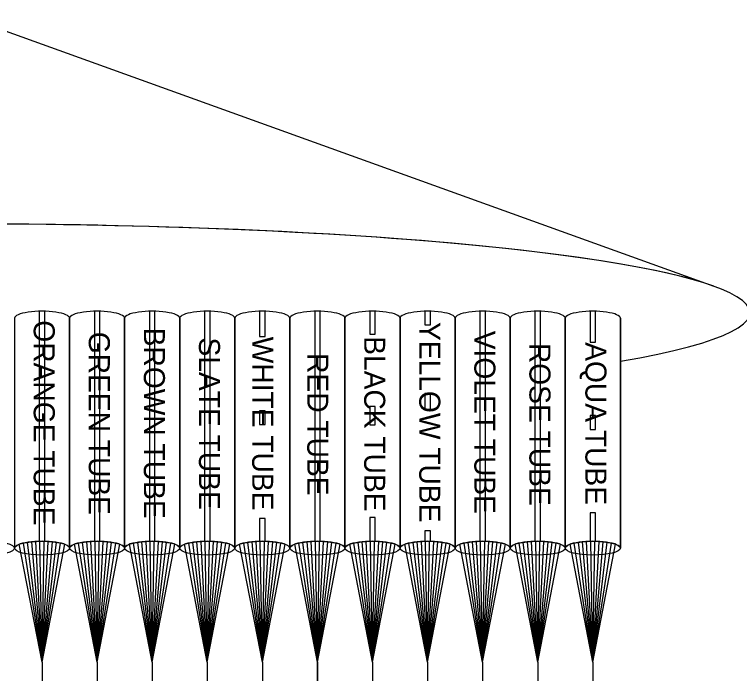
# Model space of a CAD drawing. Extents: x 1805893 to 1833564, y 708898 to 716199.
# Drawn here: x 1831827.8 to 1831906.8, y 715537.7 to 715609.5 of the extents above; entities that cross this region are included whole.
import ezdxf

# ---------------------------------------------------------------- set-up
doc = ezdxf.new("R2010")
doc.units = 0
doc.layers.add('SH_Data', color=7, linetype='Continuous')

msp = doc.modelspace()

# ---------------------------------------------------------------- linework, layer by layer
at = {"layer": 'SH_Data'}
for p, q in [((1831827.844, 715576.44), (1831827.844, 715551.39)), ((1831833.844, 715576.44), (1831833.844, 715551.39)), ((1831833.844, 715551.39), (1831833.844, 715576.44)), ((1831839.844, 715551.39), (1831839.844, 715576.44)), ((1831839.844, 715576.44), (1831839.844, 715551.39)), ((1831845.844, 715551.39), (1831845.844, 715576.44)), ((1831845.844, 715576.44), (1831845.844, 715551.39)), ((1831851.844, 715551.39), (1831851.844, 715576.44)), ((1831851.844, 715576.44), (1831851.844, 715551.39)), ((1831857.844, 715551.39), (1831857.844, 715576.44)), ((1831857.844, 715576.44), (1831857.844, 715551.39)), ((1831863.844, 715551.39), (1831863.844, 715576.44)), ((1831863.844, 715576.44), (1831863.844, 715551.39)), ((1831869.844, 715576.44), (1831869.844, 715551.39)), ((1831869.844, 715551.39), (1831869.844, 715576.44)), ((1831875.844, 715551.39), (1831875.844, 715576.44)), ((1831875.844, 715576.44), (1831875.844, 715551.39)), ((1831881.844, 715551.39), (1831881.844, 715576.44)), ((1831881.844, 715576.44), (1831881.844, 715551.39)), ((1831887.844, 715551.39), (1831887.844, 715576.44)), ((1831887.844, 715576.44), (1831887.844, 715551.39)), ((1831893.844, 715551.39), (1831893.844, 715576.44)), ((1831893.844, 715576.44), (1831893.844, 715551.39)), ((1831893.844, 715551.39), (1831893.844, 715571.748)), ((1831830.844, 715538.969), (1831828.369, 715551.813)), ((1831830.844, 715538.969), (1831828.819, 715551.943)), ((1831830.844, 715538.969), (1831829.269, 715552.028)), ((1831830.844, 715538.969), (1831829.719, 715552.085)), ((1831830.844, 715538.969), (1831830.169, 715552.12)), ((1831830.844, 715538.969), (1831830.619, 715552.137)), ((1831830.844, 715538.969), (1831831.069, 715552.137)), ((1831830.844, 715538.969), (1831831.519, 715552.12)), ((1831830.844, 715538.969), (1831831.969, 715552.085)), ((1831830.844, 715538.969), (1831832.419, 715552.028)), ((1831830.844, 715538.969), (1831832.869, 715551.943)), ((1831830.844, 715538.969), (1831833.319, 715551.813)), ((1831836.844, 715538.969), (1831834.369, 715551.813)), ((1831836.844, 715538.969), (1831834.819, 715551.943)), ((1831836.844, 715538.969), (1831835.269, 715552.028)), ((1831836.844, 715538.969), (1831835.719, 715552.085)), ((1831836.844, 715538.969), (1831836.169, 715552.12)), ((1831836.844, 715538.969), (1831836.619, 715552.137)), ((1831836.844, 715538.969), (1831837.069, 715552.137)), ((1831836.844, 715538.969), (1831837.519, 715552.12)), ((1831836.844, 715538.969), (1831837.969, 715552.085)), ((1831836.844, 715538.969), (1831838.419, 715552.028)), ((1831836.844, 715538.969), (1831838.869, 715551.943)), ((1831836.844, 715538.969), (1831839.319, 715551.813)), ((1831842.844, 715538.969), (1831840.369, 715551.813)), ((1831842.844, 715538.969), (1831840.819, 715551.943)), ((1831842.844, 715538.969), (1831841.269, 715552.028)), ((1831842.844, 715538.969), (1831841.719, 715552.085)), ((1831842.844, 715538.969), (1831842.169, 715552.12)), ((1831842.844, 715538.969), (1831842.619, 715552.137)), ((1831842.844, 715538.969), (1831843.069, 715552.137)), ((1831842.844, 715538.969), (1831843.519, 715552.12)), ((1831842.844, 715538.969), (1831843.969, 715552.085)), ((1831842.844, 715538.969), (1831844.419, 715552.028)), ((1831842.844, 715538.969), (1831844.869, 715551.943)), ((1831842.844, 715538.969), (1831845.319, 715551.813)), ((1831848.844, 715538.969), (1831846.369, 715551.813)), ((1831848.844, 715538.969), (1831846.819, 715551.943)), ((1831848.844, 715538.969), (1831847.269, 715552.028)), ((1831848.844, 715538.969), (1831847.719, 715552.085)), ((1831848.844, 715538.969), (1831848.169, 715552.12)), ((1831848.844, 715538.969), (1831848.619, 715552.137)), ((1831848.844, 715538.969), (1831849.069, 715552.137)), ((1831848.844, 715538.969), (1831849.519, 715552.12)), ((1831848.844, 715538.969), (1831849.969, 715552.085)), ((1831848.844, 715538.969), (1831850.419, 715552.028)), ((1831848.844, 715538.969), (1831850.869, 715551.943)), ((1831848.844, 715538.969), (1831851.319, 715551.813)), ((1831854.844, 715538.969), (1831852.369, 715551.813)), ((1831854.844, 715538.969), (1831852.819, 715551.943)), ((1831854.844, 715538.969), (1831853.269, 715552.028)), ((1831854.844, 715538.969), (1831853.719, 715552.085)), ((1831854.844, 715538.969), (1831854.169, 715552.12)), ((1831854.844, 715538.969), (1831854.619, 715552.137)), ((1831854.844, 715538.969), (1831855.069, 715552.137)), ((1831854.844, 715538.969), (1831855.519, 715552.12)), ((1831854.844, 715538.969), (1831855.969, 715552.085)), ((1831854.844, 715538.969), (1831856.419, 715552.028)), ((1831854.844, 715538.969), (1831856.869, 715551.943)), ((1831854.844, 715538.969), (1831857.319, 715551.813)), ((1831860.844, 715538.969), (1831858.369, 715551.813)), ((1831860.844, 715538.969), (1831858.819, 715551.943)), ((1831860.844, 715538.969), (1831859.269, 715552.028)), ((1831860.844, 715538.969), (1831859.719, 715552.085)), ((1831860.844, 715538.969), (1831860.169, 715552.12)), ((1831860.844, 715538.969), (1831860.619, 715552.137)), ((1831860.844, 715538.969), (1831861.069, 715552.137)), ((1831860.844, 715538.969), (1831861.519, 715552.12)), ((1831860.844, 715538.969), (1831861.969, 715552.085)), ((1831860.844, 715538.969), (1831862.419, 715552.028)), ((1831860.844, 715538.969), (1831862.869, 715551.943)), ((1831860.844, 715538.969), (1831863.319, 715551.813)), ((1831866.844, 715538.969), (1831864.369, 715551.813)), ((1831866.844, 715538.969), (1831864.819, 715551.943)), ((1831866.844, 715538.969), (1831865.269, 715552.028)), ((1831866.844, 715538.969), (1831865.719, 715552.085)), ((1831866.844, 715538.969), (1831866.169, 715552.12)), ((1831866.844, 715538.969), (1831866.619, 715552.137)), ((1831866.844, 715538.969), (1831867.069, 715552.137)), ((1831866.844, 715538.969), (1831867.519, 715552.12)), ((1831866.844, 715538.969), (1831867.969, 715552.085)), ((1831866.844, 715538.969), (1831868.419, 715552.028)), ((1831866.844, 715538.969), (1831868.869, 715551.943)), ((1831866.844, 715538.969), (1831869.319, 715551.813)), ((1831872.844, 715538.969), (1831870.369, 715551.813)), ((1831872.844, 715538.969), (1831870.819, 715551.943)), ((1831872.844, 715538.969), (1831871.269, 715552.028)), ((1831872.844, 715538.969), (1831871.719, 715552.085)), ((1831872.844, 715538.969), (1831872.169, 715552.12)), ((1831872.844, 715538.969), (1831872.619, 715552.137)), ((1831872.844, 715538.969), (1831873.069, 715552.137)), ((1831872.844, 715538.969), (1831873.519, 715552.12)), ((1831872.844, 715538.969), (1831873.969, 715552.085)), ((1831872.844, 715538.969), (1831874.419, 715552.028)), ((1831872.844, 715538.969), (1831874.869, 715551.943)), ((1831872.844, 715538.969), (1831875.319, 715551.813)), ((1831878.844, 715538.969), (1831876.369, 715551.813)), ((1831878.844, 715538.969), (1831876.819, 715551.943)), ((1831878.844, 715538.969), (1831877.269, 715552.028)), ((1831878.844, 715538.969), (1831877.719, 715552.085)), ((1831878.844, 715538.969), (1831878.169, 715552.12)), ((1831878.844, 715538.969), (1831878.619, 715552.137)), ((1831878.844, 715538.969), (1831879.069, 715552.137)), ((1831878.844, 715538.969), (1831879.519, 715552.12)), ((1831878.844, 715538.969), (1831879.969, 715552.085)), ((1831878.844, 715538.969), (1831880.419, 715552.028)), ((1831878.844, 715538.969), (1831880.869, 715551.943)), ((1831878.844, 715538.969), (1831881.319, 715551.813)), ((1831884.844, 715538.969), (1831882.369, 715551.813)), ((1831884.844, 715538.969), (1831882.819, 715551.943)), ((1831884.844, 715538.969), (1831883.269, 715552.028)), ((1831884.844, 715538.969), (1831883.719, 715552.085)), ((1831884.844, 715538.969), (1831884.169, 715552.12)), ((1831884.844, 715538.969), (1831884.619, 715552.137)), ((1831884.844, 715538.969), (1831885.069, 715552.137)), ((1831884.844, 715538.969), (1831885.519, 715552.12)), ((1831884.844, 715538.969), (1831885.969, 715552.085)), ((1831884.844, 715538.969), (1831886.419, 715552.028)), ((1831884.844, 715538.969), (1831886.869, 715551.943)), ((1831884.844, 715538.969), (1831887.319, 715551.813)), ((1831890.844, 715538.969), (1831888.369, 715551.813)), ((1831890.844, 715538.969), (1831888.819, 715551.943)), ((1831890.844, 715538.969), (1831889.269, 715552.028)), ((1831890.844, 715538.969), (1831889.719, 715552.085)), ((1831890.844, 715538.969), (1831890.169, 715552.12)), ((1831890.844, 715538.969), (1831890.619, 715552.137)), ((1831890.844, 715538.969), (1831891.069, 715552.137)), ((1831890.844, 715538.969), (1831891.519, 715552.12)), ((1831890.844, 715538.969), (1831891.969, 715552.085)), ((1831890.844, 715538.969), (1831892.419, 715552.028)), ((1831890.844, 715538.969), (1831892.869, 715551.943)), ((1831890.844, 715538.969), (1831893.319, 715551.813)), ((1831830.844, 715538.969), (1831830.844, 715504.211)), ((1831830.844, 715538.969), (1831830.844, 715504.211)), ((1831836.844, 715538.969), (1831836.844, 715504.211)), ((1831836.844, 715538.969), (1831836.844, 715504.211)), ((1831842.844, 715538.969), (1831842.844, 715504.211)), ((1831842.844, 715538.969), (1831842.844, 715504.211)), ((1831848.844, 715538.969), (1831848.844, 715504.211)), ((1831848.844, 715538.969), (1831848.844, 715504.211)), ((1831854.844, 715538.969), (1831854.844, 715504.211)), ((1831854.846, 715538.969), (1831854.86, 715504.211)), ((1831860.844, 715504.211), (1831860.844, 715538.969)), ((1831860.844, 715538.969), (1831860.844, 715504.211)), ((1831866.844, 715538.969), (1831866.844, 715504.211)), ((1831866.844, 715538.969), (1831866.844, 715504.211)), ((1831872.844, 715538.969), (1831872.844, 715504.211)), ((1831872.844, 715538.969), (1831872.844, 715504.211)), ((1831878.844, 715538.969), (1831878.844, 715504.211)), ((1831878.844, 715538.969), (1831878.844, 715504.211)), ((1831884.844, 715538.969), (1831884.844, 715504.211)), ((1831884.844, 715538.969), (1831884.844, 715504.211)), ((1831890.844, 715538.969), (1831890.844, 715504.211)), ((1831890.846, 715538.969), (1831890.86, 715504.211))]:
    msp.add_line(p, q, dxfattribs=at)
msp.add_lwpolyline([(1831739.647, 715579.916), (1831821.844, 715609.509), (1831904.04, 715579.916)], dxfattribs=at)
msp.add_lwpolyline([(1831739.647, 715579.916), (1831821.844, 715609.509), (1831904.04, 715579.916)], dxfattribs=at)
for points in [[(1831830.544, 715577.186), (1831830.544, 715552.138), (1831831.144, 715552.138), (1831831.144, 715577.186)], [(1831836.544, 715577.186), (1831836.544, 715552.138), (1831837.144, 715552.138), (1831837.144, 715577.186)], [(1831842.544, 715577.186), (1831842.544, 715552.138), (1831843.144, 715552.138), (1831843.144, 715577.186)], [(1831848.544, 715577.186), (1831848.544, 715552.138), (1831849.144, 715552.138), (1831849.144, 715577.186)], [(1831854.544, 715577.186), (1831854.544, 715574.46), (1831855.144, 715574.46), (1831855.144, 715577.186)], [(1831860.544, 715577.186), (1831860.544, 715552.138), (1831861.144, 715552.138), (1831861.144, 715577.186)], [(1831866.544, 715577.186), (1831866.544, 715574.709), (1831867.144, 715574.709), (1831867.144, 715577.186)], [(1831872.544, 715577.186), (1831872.544, 715575.722), (1831873.144, 715575.722), (1831873.144, 715577.186)], [(1831878.544, 715577.186), (1831878.544, 715552.138), (1831879.144, 715552.138), (1831879.144, 715577.186)], [(1831884.544, 715577.186), (1831884.544, 715552.138), (1831885.144, 715552.138), (1831885.144, 715577.186)], [(1831890.544, 715577.186), (1831890.544, 715573.818), (1831891.144, 715573.818), (1831891.144, 715577.186)], [(1831872.544, 715568.222), (1831872.544, 715566.502), (1831873.144, 715566.502), (1831873.144, 715568.222)], [(1831866.544, 715566.809), (1831866.544, 715564.837), (1831867.144, 715564.837), (1831867.144, 715566.809)], [(1831854.544, 715566.354), (1831854.544, 715564.87), (1831855.144, 715564.87), (1831855.144, 715566.354)], [(1831890.544, 715565.823), (1831890.544, 715564.305), (1831891.144, 715564.305), (1831891.144, 715565.823)], [(1831854.544, 715554.623), (1831854.544, 715552.136), (1831855.144, 715552.136), (1831855.144, 715554.623)], [(1831866.544, 715554.744), (1831866.544, 715552.136), (1831867.144, 715552.136), (1831867.144, 715554.744)], [(1831890.544, 715555.239), (1831890.544, 715552.136), (1831891.144, 715552.136), (1831891.144, 715555.239)], [(1831872.544, 715553.264), (1831872.544, 715552.136), (1831873.144, 715552.136), (1831873.144, 715553.264)]]:
    msp.add_lwpolyline(points, close=True, dxfattribs=at)
for centre, major_axis, ratio, start_param, end_param in [((1831821.844, 715577.043), (86.094, 0), 0.112175, 5.702888, 10.005075), ((1831821.844, 715577.043), (86.094, 0), 0.112175, 5.702888, 10.005075), ((1831821.844, 715577.043), (86.094, 0), 0.112175, 0.302036, 2.839557), ((1831830.844, 715576.44), (3, 0), 0.25, 0, 3.141593), ((1831830.844, 715576.44), (3, 0), 0.25, 0, 3.141593), ((1831836.844, 715576.44), (3, 0), 0.25, 0, 3.141593), ((1831836.844, 715576.44), (3, 0), 0.25, 0, 3.141593), ((1831842.844, 715576.44), (3, 0), 0.25, 0, 3.141593), ((1831842.844, 715576.44), (3, 0), 0.25, 0, 3.141593), ((1831848.844, 715576.44), (3, 0), 0.25, 0, 3.141593), ((1831848.844, 715576.44), (3, 0), 0.25, 0, 3.141593), ((1831854.844, 715576.44), (3, 0), 0.25, 0, 3.141593), ((1831854.844, 715576.44), (3, 0), 0.25, 0, 3.141593), ((1831860.844, 715576.44), (3, 0), 0.25, 0, 3.141593), ((1831860.844, 715576.44), (3, 0), 0.25, 0, 3.141593), ((1831866.844, 715576.44), (3, 0), 0.25, 0, 3.141593), ((1831866.844, 715576.44), (3, 0), 0.25, 0, 3.141593), ((1831872.844, 715576.44), (3, 0), 0.25, 0, 3.141593), ((1831872.844, 715576.44), (3, 0), 0.25, 0, 3.141593), ((1831878.844, 715576.44), (3, 0), 0.25, 0, 3.141593), ((1831878.844, 715576.44), (3, 0), 0.25, 0, 3.141593), ((1831884.844, 715576.44), (3, 0), 0.25, 0, 3.141593), ((1831884.844, 715576.44), (3, 0), 0.25, 0, 3.141593), ((1831890.844, 715576.44), (3, 0), 0.25, 0, 3.141593), ((1831890.844, 715576.44), (3, 0), 0.25, 0, 3.141593), ((1831830.844, 715551.39), (3, 0), 0.25, 0, 3.141593), ((1831836.844, 715551.39), (3, 0), 0.25, 0, 3.141593), ((1831842.844, 715551.39), (3, 0), 0.25, 0, 3.141593), ((1831848.844, 715551.39), (3, 0), 0.25, 0, 3.141593), ((1831854.844, 715551.39), (3, 0), 0.25, 0, 3.141593), ((1831860.844, 715551.39), (3, 0), 0.25, 0, 3.141593), ((1831866.844, 715551.39), (3, 0), 0.25, 0, 3.141593), ((1831872.844, 715551.39), (3, 0), 0.25, 0, 3.141593), ((1831878.844, 715551.39), (3, 0), 0.25, 0, 3.141593), ((1831884.844, 715551.39), (3, 0), 0.25, 0, 3.141593), ((1831890.844, 715551.39), (3, 0), 0.25, 0, 3.141593)]:
    msp.add_ellipse(centre, major_axis=major_axis, ratio=ratio, start_param=start_param, end_param=end_param, dxfattribs=at)
for centre in [(1831824.844, 715551.39), (1831830.844, 715551.39), (1831836.844, 715551.39), (1831842.844, 715551.39), (1831848.844, 715551.39), (1831854.844, 715551.39), (1831860.844, 715551.39), (1831866.844, 715551.39), (1831872.844, 715551.39), (1831878.844, 715551.39), (1831884.844, 715551.39), (1831890.844, 715551.39)]:
    msp.add_ellipse(centre, major_axis=(3, 0), ratio=0.25, dxfattribs=at)

# ---------------------------------------------------------------- texts
for s, height, p in [('ORANGE TUBE', 2.29468, (1831829.936, 715576.205)), ('YELLOW TUBE', 2.29468, (1831871.936, 715576.019)), ('BROWN TUBE', 2.2947, (1831841.936, 715575.402)), ('GREEN TUBE', 2.2947, (1831835.936, 715574.958)), ('WHITE TUBE', 2.2947, (1831853.735, 715574.421)), ('VIOLET TUBE', 2.29468, (1831877.936, 715575.069)), ('SLATE TUBE', 2.2947, (1831847.936, 715574.336)), ('BLACK TUBE', 2.2947, (1831865.936, 715574.475)), ('AQUA TUBE', 2.2947, (1831890.036, 715573.822)), ('ROSE TUBE', 2.2947, (1831883.936, 715573.746)), ('RED TUBE', 2.2947, (1831859.735, 715572.633))]:
    msp.add_text(s, height=height, rotation=270, dxfattribs=at).set_placement(p)

doc.saveas('drawing.dxf')
